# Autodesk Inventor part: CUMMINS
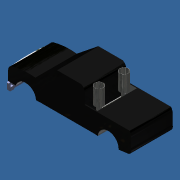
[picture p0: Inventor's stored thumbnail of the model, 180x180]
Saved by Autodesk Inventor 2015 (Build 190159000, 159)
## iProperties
Created: 2014-10
Part Number: CUMMINS
Material: Generic
Document SubType Name: Modeling
Designer: caovt
Density: 1 g/cm^3
Appearance: Chrome - Polished Black
Author: caovt
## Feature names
1. Extrusion1
2. Extrusion6
3. Mirror2
4. Extrusion7
5. Mirror3
6. Extrusion8
7. Extrusion9
8. Extrusion12
9. Extrusion13
10. Extrusion14
11. Extrusion15
12. Fillet1
13. Extrusion16
14. Extrusion17
15. Extrusion18
16. Extrusion19
17. Sweep3
18. Sweep4
19. Mirror6
20. Extrusion20
21. Mirror9
22. Extrusion21
23. Mirror10
24. Extrusion22
25. Mirror11
26. Sweep8
27. Mirror15
## Parameters: d1 = 330.2 mm, d6 = 88.9 mm, d27 = 101.6 mm, d28 = 0, d48 = 50.8 mm, d49 = 50.8 mm, d50 = 50.8 mm, d51 = 50.8 mm, d52 = 25.4 mm, d53 = 0, d54 = 15.875 mm, d55 = 12.7 mm, d56 = 12.7 mm, d57 = 0, d58 = 25.4 mm, d59 = 0, d60 = 25.4 mm, d61 = 0, d62 = 6.35 mm, d66 = 12.7 mm, d67 = 15.875 mm, d68 = 6.35 mm, d69 = 15.875 mm, d70 = 25.4 mm, d71 = 0, d72 = 25.4 mm, d73 = 0, d74 = 25.4 mm, d75 = 0, d76 = 20.32 mm, d77 = 20.32 mm, d78 = 6.35 mm, d79 = 25.4 mm, d80 = 0, d128 = 25.4 mm, d129 = 0, d175 = 2.54 mm, d176 = 0, d191 = 2.54 mm, d192 = 0, d221 = 102.63956 mm, d222 = 5.08 mm, d223 = 0, d228 = 12.7 mm, d230 = 17.78 mm, d231 = 17.78 mm, d232 = 6.35 mm, d233 = 4.445 mm, d234 = 4.445 mm, d235 = 0.3048 mm, d236 = 0, d243 = 0.3048 mm, d244 = 0, d245 = 25.4 mm, d246 = 0, d250 = 2.54 mm, d251 = 2.54 mm, d252 = 25.4 mm, d253 = 0, d254 = 10.16 mm, d255 = 0, d256 = 0, d257 = 0, d259 = 25.4 mm, d260 = 10.16 mm, d261 = 0, d262 = 0, d269 = 28.575 mm, d274 = 0, d275 = 0, d280 = 3.175 mm, d281 = 20 deg, d282 = 1.27 mm, d283 = 60 deg, d284 = 1.27 mm, d285 = 60 deg, d295 = 0, d296 = 20.32 mm, d297 = 0, d298 = 0
